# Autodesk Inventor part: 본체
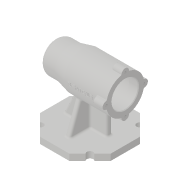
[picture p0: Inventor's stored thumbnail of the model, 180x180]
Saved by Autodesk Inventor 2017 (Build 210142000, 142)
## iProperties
Created: 2019-12
Part Number: 본체
Material: Generic
Document SubType Name: Modeling
Designer: 5-08-le
Density: 1 g/cm^3
Appearance: Default
Author: 5-08-le
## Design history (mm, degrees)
sketch "스케치1" dims "d0" = 112
  geometry: L1 (56, -23.196)-(23.196, -56); L2 (23.196, -56)-(-23.196, -56); L3 (-23.196, -56)-(-56, -23.196); L4 (-56, -23.196)-(-56, 23.196); L5 (-56, 23.196)-(-23.196, 56); L6 (-23.196, 56)-(23.196, 56); L7 (23.196, 56)-(56, 23.196); L8 (56, 23.196)-(56, -23.196); C1 r 5 at (39.598, 39.598); C2 r 5 at (39.598, -39.598); C3 r 5 at (-39.598, -39.598); C4 r 5 at (-39.598, 39.598); 4 further points
  constraints: 16 end point, 5 midpoint, 4 centre point, 3 equal radius, 2 coincident, 1 horizontal alignment, 19 other
  dimensions: "d1" = 10 diameter of C1
extrude "돌출1" new body sketch "스케치1" distance "d2" = 10; taper "d3" = 0 deg
extrude "돌출2" cut sketch "스케치1" distance "d4" = 10; taper "d5" = 0 deg
sketch "스케치2"
  geometry: L1 (56, 80)-(-11, 80); L2 (-11, 80)-(-11, 110); L3 (-11, 110)-(56, 110); L4 (56, 110)-(56, 80); L5 (-11, 80)-(-56, 80); L6 (-56, 80)-(-56, 105); L7 (-56, 105)-(-11, 105); L8 (-11, 105)-(-11, 80); L9 (56, 0)-(56, 10) reference; L10 (56, 0)-(43.134, 0) reference; L11 (-11, 110)-(-31, 105); 2 further points
  constraints: 18 end point, 4 parallel, 2 horizontal, 2 perpendicular, 1 collinear, 1 midpoint, 1 point on line
  dimensions: "d6" = 80 distance from line of L10 L1.start; "d7" = 112 distance between parallel lines of L6 L4; "d8" = 45 distance between parallel lines of L6 L2; "d9" = 60 diameter of L3 L1; "d10" = 50 diameter of L7 L5; "d77" = 25 distance from line of L11.end L6
revolve "회전1" sketch "스케치2" stored, may be unused: angle "d11" = 90 deg
sketch "스케치9"
  geometry: L1 (-38, 10)-(-16.012, 57.154); L2 (-16.012, 57.154)-(31, 57.154); L3 (-34.598, 0)-(-34.598, 10) reference; L4 (31, 57.154)-(31, 10); L5 (31, 10)-(-38, 10); L6 (34.598, 10)-(43.134, 10) reference; L7 (56, 0)-(56, 10) reference; L8 (-56, 0)-(-56, 10) reference; L9 (-43.134, 10)-(-34.598, 10) reference; 3 further points
  constraints: 8 end point, 1 collinear, 1 perpendicular, 1 vertical
  dimensions: "d50" = 25 distance between parallel lines of L4 L7; "d51" = 18 distance from line of L1.start L8; "d52" = 115 deg angle of L9 L1
extrude "돌출5" join sketch "스케치9" stored distance "d53" = 8; taper "d54" = 0 deg
sketch "스케치10"
  geometry: L1 (10, 36)-(46.824, 22.597); L2 (0, 56)-(10, 56) reference; L3 (10, 43.134)-(10, 56) reference; L4 (10, 43.134)-(10, 34.598) reference; 2 further points
  constraints: 2 end point, 1 point on line
  dimensions: "d55" = 20 distance from line of L1.start L2; "d56" = 110 deg angle of L3 L1
feature "리브1" sketch "스케치10" dims "d57" = 1, "d58" = 8, "d59" = 0, "d60" = 0, "d61" = 1, "d62" = 1
sketch "스케치3"
  geometry: L1 (56, 80)-(41, 80); L2 (41, 80)-(41, 101); L3 (41, 101)-(56, 101); L4 (56, 101)-(56, 80); L5 (41, 80)-(-13, 80); L6 (-13, 80)-(-13, 101); L7 (-10, 104)-(38, 104); L8 (41, 101)-(41, 80); L9 (-13, 80)-(-25, 80); L10 (-25, 80)-(-25, 100.7); L11 (-24.7, 101)-(-13, 101); L12 (-13, 101)-(-13, 80); L13 (-25, 80)-(-43, 80); L14 (-43, 80)-(-43, 97.2); L15 (-42.7, 97.5)-(-25, 97.5); L16 (-25, 97.5)-(-25, 80); L17 (-47, 80)-(-50, 80); L18 (-50, 80)-(-50, 90.5); L19 (-47, 90.5)-(-47, 80); L20 (-43, 80)-(-47, 80); L21 (-47, 80)-(-47, 95.7); L22 (-46.7, 96)-(-43, 96); L23 (-43, 96)-(-43, 80); L24 (43.134, 0)-(56, 0) reference; L25 (-47, 90.5)-(-50, 90.5); L26 (56, 50)-(56, 110) reference; A1 r 3 centre (38, 101) between (41, 101) and (38, 104); A2 r 3 centre (-10, 101) between (-10, 104) and (-13, 101); A3 r 0.3 centre (-46.7, 95.7) between (-46.7, 96) and (-47, 95.7); A4 r 0.3 centre (-42.7, 97.2) between (-42.7, 97.5) and (-43, 97.2); A5 r 0.3 centre (-24.7, 100.7) between (-24.7, 101) and (-25, 100.7); 6 further points
  constraints: 48 end point, 12 point on line, 11 parallel, 10 point on circle, 10 tangent, 7 horizontal, 6 perpendicular, 5 centre point, 3 equal radius, 1 collinear
  dimensions: "d12" = 80 distance from line of L24 L1.start; "d13" = 42 diameter of L3 L1; "d14" = 15 distance of L2.end L3.end; "d15" = 48 diameter of L7 L5; "d16" = 54 distance of point (-13, 104) point (41, 104); "d17" = 42 diameter of L11 L9; "d18" = 12 distance of point (-25, 101) L11.end; "d19" = 21 diameter of L25 L17; "d20" = 3 distance of L19.start L18.end; "d21" = 32 diameter of L22 L20; "d22" = 4 distance of point (-47, 96) L22.end; "d23" = 18 distance of point (-43, 97.5) L15.end; "d24" = 35 diameter of L15 L13; "d25" = 3 radius of A1; "d26" = 0.3 radius of A3
revolve "회전2" sketch "스케치3" stored, may be unused: angle "d27" = 90 deg
sketch "스케치4"
  geometry: C1 r 6 at (0, 30); 2 further points
  constraints: 1 centre point, 1 vertical alignment, 1 other
  dimensions: "d28" = 12 diameter of C1
extrude "돌출3" join sketch "스케치4" distance "d29" = 16; taper "d30" = 0 deg
sketch "스케치5"
  geometry: A1 r 6 centre (0, 0) between (5.97, -0.6) and (-5.97, -0.6) reference; A2 r 6 centre (-30, -30) between (-29.4, -24.03) and (-29.4, -35.97) reference; A3 r 6 centre (0, -60) between (-5.97, -59.4) and (5.97, -59.4) reference; A4 r 6 centre (30, -30) between (29.4, -35.97) and (29.4, -24.03) reference; 1 further point
hole "구멍1" sketch "스케치5" at (30, -30), (0, -60), (0, 0), (-30, -30) diameter "d34" = 3.242; stored, may be unused: countersink angle "d38" = 90 deg, drill point angle "d40" = 118 deg; dims "d35" = 8, "d36" = 4, "d37" = 2, "d39" = 11
fillet "모깎기1" dims "d63" = 3
chamfer "모따기1" distance "d64" = 1; stored, may be unused: second distance "d65" = 2, angle "d66" = 45 deg
fillet "모깎기2" dims "d67" = 10
fillet "모깎기3" dims "d68" = 3
fillet "모깎기4" dims "d69" = 3
fillet "모깎기5" dims "d70" = 3
fillet "모깎기6" dims "d71" = 1
sketch "스케치11"
  geometry: L1 (59.258, 0)-(46.392, 0) reference; L2 (79.196, 86.771)-(79.196, 109.226) reference; 2 further points
  constraints: 1 other
  dimensions: "d73" = 80 distance from line of point (38.196, 80) L1; "d74" = 41 distance from line of point (38.196, 80) L2
feature "엠보싱1" sketch "스케치11" dims "d6" = 80, "d7" = 112, "d8" = 45, "d9" = 60, "d10" = 50, "d75" = 0.5, "d76" = 0, "d77" = 25
fillet "모깎기8" dims "d78" = 3
fillet "모깎기9" dims "d79" = 3
fillet "모깎기10" dims "d80" = 3
node "솔리드1"
mirror "미러1"
pattern_circular "원형 패턴1" dims angle "d32" = 360 deg
